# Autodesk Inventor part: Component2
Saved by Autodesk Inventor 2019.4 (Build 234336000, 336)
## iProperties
Created: 2020-06
Part Number: Component2
Material: Generic
Document SubType Name: Modeling
Designer: Administrator
Density: 1 g/cm^3
Appearance: Default
Title: Component2
Author: Administrator
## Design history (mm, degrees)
